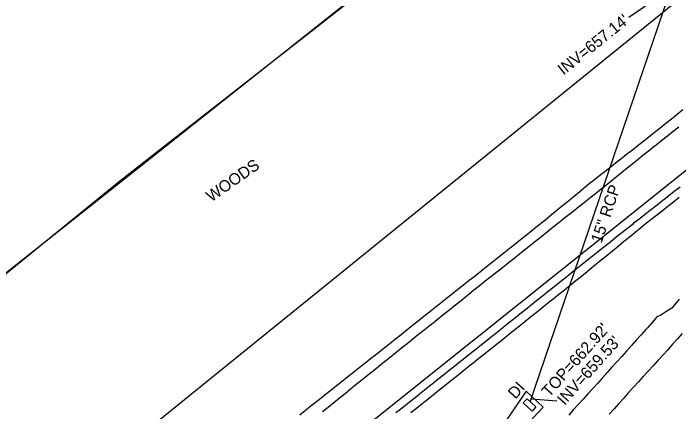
# Model space of a CAD drawing. Extents: x 1806071 to 1809844, y 912722 to 917035.
# Drawn here: x 1808248.8 to 1808478, y 915395 to 915532.3 of the extents above; entities that cross this region are included whole.
import ezdxf

# ---------------------------------------------------------------- set-up
doc = ezdxf.new("R2010")
doc.units = 0
for name, color, linetype in [('Exist Horizontal Alignment', 7, 'Continuous'), ('Exist Other Culture Fence Line', 7, 'Continuous'), ('Exist Right of Way Line', 7, 'Continuous'), ('Exist Roads EOP', 7, 'Continuous'), ('Exist Roads EOT', 7, 'Continuous'), ('Exist Structure Minor Drop Inlet', 7, 'Continuous'), ('Exist Structure Minor Drop Inlet Text', 7, 'Continuous'), ('Exist Structure Minor Drop Inlet Top Elevation', 7, 'Continuous'), ('Exist Structure Minor Paved Ditch or Gutter', 7, 'Continuous'), ('Exist Structure Minor Pipes RCP 15 Inch', 7, 'Continuous'), ('Exist Structure Minor Pipes RCP 15 Inch Invert', 7, 'Continuous'), ('Exist Structure Minor Pipes RCP 15 Inch Text', 7, 'Continuous'), ('Exist Vegetation Woods Line', 7, 'Continuous'), ('Exist Vegetation Woods Line Text', 7, 'Continuous')]:
    doc.layers.add(name, color=color, linetype=linetype)

msp = doc.modelspace()

# ---------------------------------------------------------------- linework, layer by layer
at = {"layer": 'Exist Horizontal Alignment'}
msp.add_line((1808496.99, 915491.27), (1807817.19, 914947.49), dxfattribs=at)
at = {"layer": 'Exist Other Culture Fence Line'}
msp.add_lwpolyline([(1807923.84, 915242.07), (1807923.27, 915185.61), (1807939.59, 915198.52), (1808032.61, 915272.97), (1808171.73, 915381.93), (1808285.98, 915474.86), (1808403.41, 915566.83), (1808512.77, 915674.68)], dxfattribs=at)
at = {"layer": 'Exist Right of Way Line'}
msp.add_line((1807941.54, 915201.11), (1808403.76, 915567.8), dxfattribs=at)
at = {"layer": 'Exist Roads EOP'}
for points in [[(1808479.44, 915498.94), (1808477.49, 915497.37), (1808475.54, 915495.81), (1808473.59, 915494.25), (1808471.63, 915492.69), (1808469.68, 915491.13), (1808467.73, 915489.57), (1808466.02, 915488.2), (1808464.05, 915486.66), (1808462.09, 915485.11), (1808460.12, 915483.57), (1808458.15, 915482.03), (1808456.19, 915480.48), (1808454.22, 915478.94), (1808452.25, 915477.4), (1808450.28, 915475.86), (1808448.32, 915474.31), (1808447.8, 915473.91), (1808445.87, 915472.32), (1808443.94, 915470.74), (1808442.01, 915469.15), (1808440.08, 915467.56), (1808438.15, 915465.97), (1808436.21, 915464.39), (1808434.28, 915462.8), (1808432.35, 915461.21), (1808431.35, 915460.39), (1808429.39, 915458.84), (1808427.44, 915457.28), (1808425.48, 915455.72), (1808423.52, 915454.17), (1808421.56, 915452.61), (1808419.61, 915451.06), (1808417.65, 915449.5), (1808415.69, 915447.94), (1808413.74, 915446.39), (1808411.78, 915444.83), (1808409.82, 915443.28), (1808407.87, 915441.72), (1808405.91, 915440.17), (1808403.95, 915438.61), (1808402, 915437.05), (1808400.04, 915435.5), (1808398.08, 915433.94), (1808396.12, 915432.39), (1808394.17, 915430.83), (1808392.21, 915429.28), (1808390.25, 915427.72), (1808388.3, 915426.16), (1808386.34, 915424.61), (1808384.38, 915423.05), (1808382.43, 915421.5), (1808380.47, 915419.94), (1808378.51, 915418.38), (1808376.56, 915416.83), (1808374.6, 915415.27), (1808372.64, 915413.72), (1808371.9, 915413.13), (1808369.94, 915411.58), (1808367.98, 915410.03), (1808366.02, 915408.48), (1808364.06, 915406.93), (1808362.1, 915405.38), (1808360.13, 915403.83), (1808358.17, 915402.28), (1808356.21, 915400.73), (1808354.25, 915399.19), (1808352.29, 915397.64), (1808351.4, 915396.93), (1808349.45, 915395.37), (1808347.5, 915393.81)], [(1808385.78, 915394.63), (1808387.74, 915396.21), (1808389.69, 915397.77), (1808391.64, 915399.33), (1808393.6, 915400.89), (1808395.55, 915402.45), (1808397.51, 915404.01), (1808399.46, 915405.57), (1808401.41, 915407.13), (1808403.37, 915408.69), (1808405.32, 915410.25), (1808407.27, 915411.81), (1808409.23, 915413.37), (1808411.18, 915414.93), (1808413.13, 915416.49), (1808413.34, 915416.65), (1808415.29, 915418.21), (1808417.23, 915419.78), (1808419.18, 915421.35), (1808421.13, 915422.91), (1808423.08, 915424.48), (1808425.03, 915426.04), (1808426.98, 915427.61), (1808428.93, 915429.17), (1808430.88, 915430.74), (1808432.83, 915432.31), (1808434.77, 915433.87), (1808436.72, 915435.44), (1808438.67, 915437), (1808440.62, 915438.57), (1808442.57, 915440.14), (1808444.52, 915441.7), (1808446.47, 915443.27), (1808447.48, 915444.08), (1808449.41, 915445.66), (1808451.34, 915447.24), (1808453.28, 915448.83), (1808455.21, 915450.41), (1808457.15, 915451.99), (1808459.08, 915453.58), (1808461.02, 915455.16), (1808462.95, 915456.75), (1808464.88, 915458.33), (1808466.43, 915459.6), (1808468.4, 915461.14), (1808470.36, 915462.69), (1808472.33, 915464.23), (1808474.29, 915465.78), (1808476.25, 915467.33), (1808478.22, 915468.87)], [(1808478.21, 915433.76), (1808476.63, 915431.82), (1808475.68, 915430.66), (1808473.56, 915429.33), (1808471.88, 915428.26), (1808470.56, 915427.61), (1808468.91, 915425.73), (1808467.26, 915423.85), (1808466.77, 915423.29), (1808465.09, 915421.43), (1808463.42, 915419.57), (1808461.75, 915417.72), (1808460.07, 915415.86), (1808458.4, 915414), (1808456.73, 915412.14), (1808455.06, 915410.29), (1808453.38, 915408.43), (1808451.71, 915406.57), (1808450.04, 915404.71), (1808448.57, 915403.08), (1808446.89, 915401.23), (1808445.21, 915399.38), (1808443.53, 915397.53), (1808441.85, 915395.67), (1808440.17, 915393.82)]]:
    msp.add_lwpolyline(points, dxfattribs=at)
at = {"layer": 'Exist Roads EOT'}
for points in [[(1808478.13, 915493.03), (1808476.17, 915491.47), (1808474.21, 915489.92), (1808472.24, 915488.37), (1808470.28, 915486.82), (1808468.32, 915485.27), (1808468.14, 915485.12), (1808466.19, 915483.56), (1808464.24, 915481.99), (1808462.29, 915480.43), (1808460.34, 915478.86), (1808458.39, 915477.29), (1808456.45, 915475.73), (1808454.5, 915474.16), (1808453.29, 915473.19), (1808451.34, 915471.63), (1808449.38, 915470.07), (1808447.43, 915468.51), (1808445.47, 915466.96), (1808443.52, 915465.4), (1808441.57, 915463.84), (1808440.71, 915463.16), (1808438.75, 915461.6), (1808436.79, 915460.05), (1808434.84, 915458.5), (1808432.88, 915456.94), (1808430.92, 915455.39), (1808428.96, 915453.84), (1808427, 915452.28), (1808425.04, 915450.73), (1808423.16, 915449.24), (1808421.2, 915447.68), (1808419.25, 915446.13), (1808417.29, 915444.57), (1808415.34, 915443.01), (1808413.38, 915441.46), (1808411.42, 915439.9), (1808409.47, 915438.34), (1808407.51, 915436.79), (1808406.5, 915435.98), (1808404.54, 915434.42), (1808402.59, 915432.86), (1808400.64, 915431.29), (1808398.69, 915429.73), (1808396.74, 915428.17), (1808394.79, 915426.6), (1808392.84, 915425.04), (1808390.88, 915423.48), (1808390.37, 915423.07), (1808388.42, 915421.51), (1808386.48, 915419.94), (1808384.53, 915418.38), (1808382.58, 915416.81), (1808380.63, 915415.24), (1808378.68, 915413.68), (1808376.73, 915412.11), (1808374.78, 915410.55), (1808372.83, 915408.98), (1808370.88, 915407.42), (1808368.93, 915405.85), (1808366.98, 915404.29), (1808365.03, 915402.72), (1808363.08, 915401.16), (1808361.13, 915399.59), (1808359.19, 915398.03), (1808357.24, 915396.46), (1808355.29, 915394.9)], [(1808380.6, 915394.65), (1808381.34, 915395.25), (1808383.3, 915396.8), (1808385.25, 915398.36), (1808387.21, 915399.91), (1808389.17, 915401.47), (1808391.13, 915403.02), (1808393.08, 915404.58), (1808395.04, 915406.13), (1808397, 915407.69), (1808398.96, 915409.24), (1808400.91, 915410.8), (1808402.87, 915412.35), (1808404.83, 915413.91), (1808406.79, 915415.46), (1808408.74, 915417.02), (1808410.7, 915418.57), (1808412.66, 915420.12), (1808413.58, 915420.86), (1808415.54, 915422.42), (1808417.49, 915423.98), (1808419.44, 915425.54), (1808421.4, 915427.1), (1808423.35, 915428.66), (1808425.3, 915430.22), (1808427.26, 915431.78), (1808429.21, 915433.34), (1808431.17, 915434.9), (1808433.12, 915436.46), (1808435.07, 915438.02), (1808437.03, 915439.58), (1808438.98, 915441.14), (1808440.93, 915442.7), (1808442.89, 915444.26), (1808444.84, 915445.82), (1808446.79, 915447.38), (1808448.75, 915448.94), (1808450.7, 915450.5), (1808452.65, 915452.06), (1808454.61, 915453.62), (1808456.56, 915455.18), (1808458.51, 915456.74), (1808460.47, 915458.3), (1808462.42, 915459.86), (1808462.75, 915460.13), (1808464.72, 915461.67), (1808466.69, 915463.21), (1808468.66, 915464.75), (1808470.63, 915466.29), (1808472.6, 915467.83), (1808474.56, 915469.37), (1808476.53, 915470.91), (1808478.5, 915472.46)], [(1808479.29, 915421.88), (1808477.61, 915420.03), (1808475.93, 915418.18), (1808474.25, 915416.33), (1808472.57, 915414.48), (1808470.89, 915412.63), (1808469.21, 915410.78), (1808467.53, 915408.93), (1808465.84, 915407.08), (1808464.16, 915405.23), (1808462.48, 915403.38), (1808460.8, 915401.53), (1808459.12, 915399.68), (1808457.44, 915397.83), (1808455.76, 915395.98), (1808454.08, 915394.13)]]:
    msp.add_lwpolyline(points, dxfattribs=at)
at = {"layer": 'Exist Structure Minor Drop Inlet'}
msp.add_lwpolyline([(1808425.81, 915399.43), (1808428.85, 915396.65), (1808427.52, 915395.19), (1808424.47, 915397.97)], close=True, dxfattribs=at)
at = {"layer": 'Exist Structure Minor Paved Ditch or Gutter'}
msp.add_lwpolyline([(1808416.91, 915389.45), (1808403.41, 915374.47), (1808404.81, 915373.02), (1808407.47, 915370.29), (1808421.19, 915385.69), (1808431.36, 915396.48), (1808425.49, 915401.99), (1808416.91, 915389.45)], dxfattribs=at)
at = {"layer": 'Exist Structure Minor Pipes RCP 15 Inch'}
msp.add_line((1808474.99, 915539.87), (1808426.71, 915398.2), dxfattribs=at)
at = {"layer": 'Exist Structure Minor Pipes RCP 15 Inch Invert'}
for p, q in [((1808473.93, 915539.8), (1808460.92, 915530.82)), ((1808427.35, 915399.36), (1808436.01, 915398.65))]:
    msp.add_line(p, q, dxfattribs=at)
at = {"layer": 'Exist Vegetation Woods Line'}
msp.add_lwpolyline([(1808500.82, 915704.61), (1808491.21, 915625.56), (1808495.36, 915566.18), (1808486.21, 915543.62), (1808230.53, 915336.55), (1808200.13, 915312.12), (1808141.53, 915267.56), (1808103.92, 915240.43), (1808069.03, 915211.34), (1808049.63, 915201.52), (1807994.2, 915144.45), (1807942.37, 915137.01), (1807895.45, 915162.79), (1807892.83, 915181.85), (1807930.19, 915207.19), (1807959.19, 915218.2), (1807984.75, 915260.79), (1807978.92, 915284.25), (1807953.04, 915291.1), (1807936.72, 915324.51), (1807911.11, 915525.74), (1807909.65, 915561.81), (1807936.43, 915572.07)], dxfattribs=at)

# ---------------------------------------------------------------- texts
at = {"layer": 'Exist Structure Minor Drop Inlet Text'}
msp.add_text('DI', height=4, rotation=47.6116, dxfattribs=at).set_placement((1808421.79, 915399.07))
at = {"layer": 'Exist Structure Minor Drop Inlet Top Elevation'}
msp.add_text("TOP=662.92'", height=4, rotation=48.2731, dxfattribs=at).set_placement((1808433.44, 915399.71))
at = {"layer": 'Exist Structure Minor Pipes RCP 15 Inch Invert'}
for s, rotation, p in [("INV=657.14'", 38.741, (1808438.36, 915510.74)), ("INV=659.53'", 48.1929, (1808438.74, 915396.93))]:
    msp.add_text(s, height=4, rotation=rotation, dxfattribs=at).set_placement(p)
at = {"layer": 'Exist Structure Minor Pipes RCP 15 Inch Text'}
msp.add_text('15" RCP', height=4, rotation=71.1823, dxfattribs=at).set_placement((1808451.42, 915452.79))
at = {"layer": 'Exist Vegetation Woods Line Text'}
msp.add_text('WOODS', height=4, rotation=35.1898, dxfattribs=at).set_placement((1808317.03, 915467.07))

doc.saveas('drawing.dxf')
